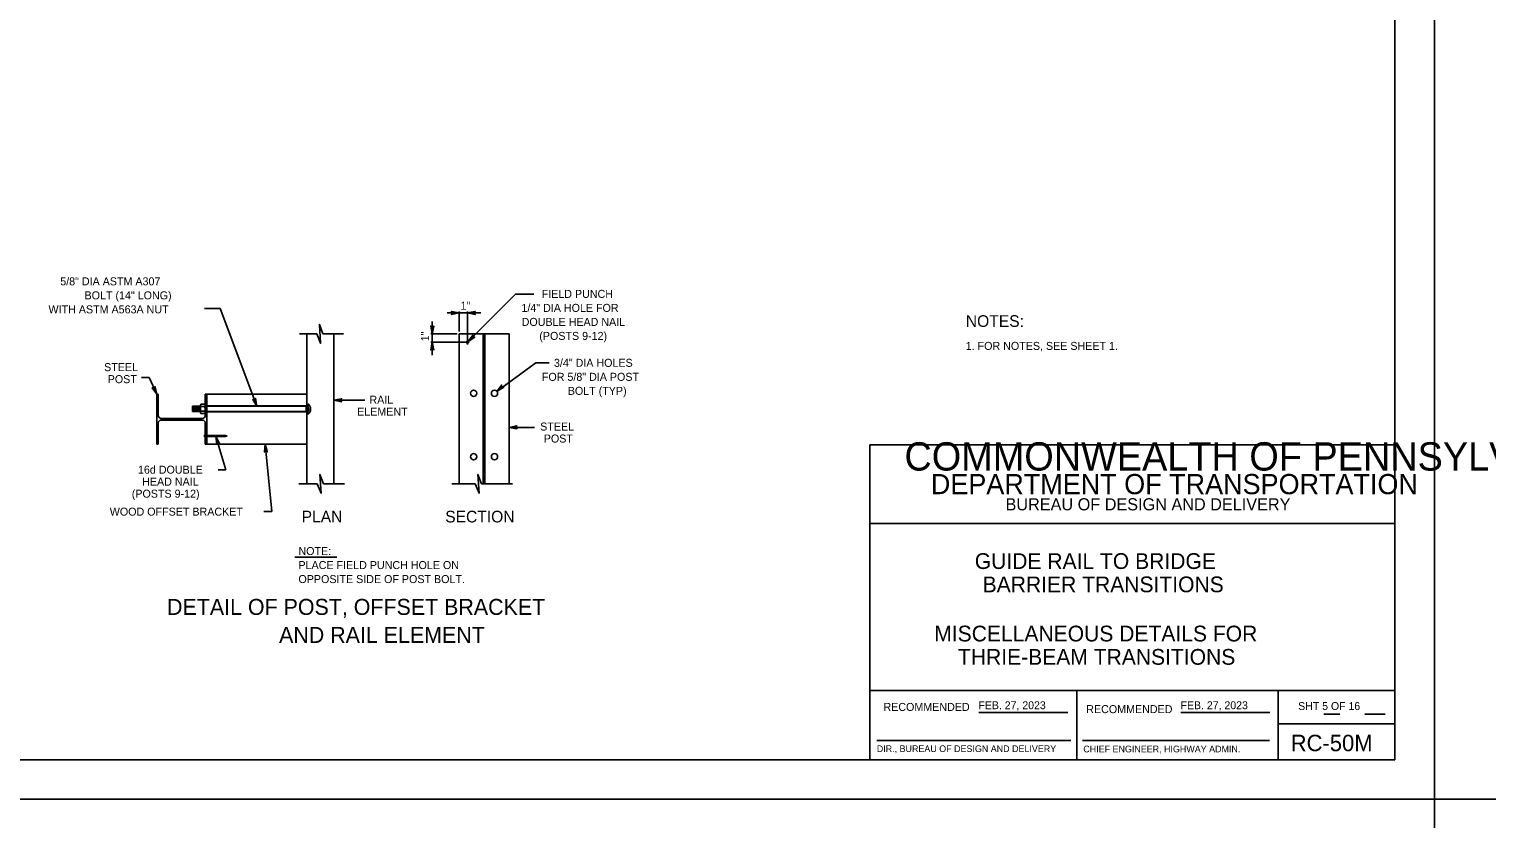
# Model space of a CAD drawing. Extents: x 632007860 to 635435983, y 295418622 to 297794622.
# Drawn here: x 633154598 to 633709860, y 297193122 to 297493872 of the extents above; entities that cross this region are included whole.
import ezdxf

# ---------------------------------------------------------------- set-up
doc = ezdxf.new("R2010")
doc.units = 0
for name, color, linetype in [('1', 7, 'Continuous'), ('2', 7, 'Continuous'), ('4', 7, 'Continuous'), ('8', 7, 'Continuous'), ('PLT-BNDY', 7, 'Continuous'), ('S-DETL-DIMS', 7, 'Continuous'), ('S-DETL-T120', 7, 'Continuous'), ('S-DETL-T175', 7, 'Continuous'), ('S-DETL-T240', 7, 'Continuous'), ('S-STEL', 7, 'Continuous')]:
    doc.layers.add(name, color=color, linetype=linetype)

msp = doc.modelspace()

# ---------------------------------------------------------------- linework, layer by layer
at = {"layer": '1'}
for p, q in [((633674860, 297779622), (633674860, 297215622)), ((633674860, 297335622), (633474860, 297335622)), ((633474860, 297335622), (633474860, 297215622)), ((633674860, 297305622), (633474860, 297305622)), ((633674860, 297241981), (633474860, 297241981)), ((633553661, 297241981), (633553661, 297215622)), ((633630362, 297241981), (633630362, 297215622)), ((633516325, 297233611), (633550211, 297233611)), ((633593323, 297233611), (633627193, 297233611)), ((633647751, 297232991), (633653893, 297232991)), ((633663427, 297232991), (633671073, 297232991)), ((633630362, 297229300), (633674860, 297229300)), ((633477485, 297222918), (633551385, 297222918)), ((633555791, 297222918), (633627131, 297222918)), ((633674860, 297215622), (632888860, 297215622))]:
    msp.add_line(p, q, dxfattribs=at)
at = {"layer": '4'}
msp.add_line((633674860, 297215622), (633674860, 297335622), dxfattribs=at)
at = {"layer": '8'}
for p, q in [((633321543, 297386319), (633321543, 297373807)), ((633307575, 297374671), (633322220, 297374671))]:
    msp.add_line(p, q, dxfattribs=at)
at = {"layer": 'PLT-BNDY'}
for points in [[(632848860, 297794622), (633689860, 297794622), (633689860, 297200622), (632848860, 297200622)], [(633689860, 297794622), (634530860, 297794622), (634530860, 297200622), (633689860, 297200622)], [(632848860, 297200622), (633689860, 297200622), (633689860, 296606622), (632848860, 296606622)], [(633689860, 297200622), (634530860, 297200622), (634530860, 296606622), (633689860, 296606622)]]:
    msp.add_lwpolyline(points, close=True, dxfattribs=at)
at = {"layer": 'S-DETL-DIMS'}
for p, q in [((633321867, 297374899), (633339865, 297392908)), ((633339865, 297392908), (633346851, 297392908)), ((633221416, 297387509), (633227417, 297387509)), ((633227417, 297387509), (633241365, 297350262)), ((633308154, 297382590), (633308154, 297369762)), ((633313856, 297385809), (633326612, 297385809)), ((633318370, 297378720), (633318370, 297386319)), ((633257604, 297377845), (633264140, 297377845)), ((633266521, 297377845), (633274387, 297377845)), ((633317648, 297377845), (633307575, 297377845)), ((633332810, 297355940), (633347545, 297366731)), ((633347545, 297366731), (633352662, 297366731)), ((633197435, 297361156), (633200307, 297361156)), ((633200307, 297361156), (633203201, 297354825)), ((633270659, 297352543), (633282501, 297352543)), ((633229477, 297326031), (633225743, 297338769)), ((633337420, 297342215), (633347032, 297342215)), ((633247091, 297310205), (633244447, 297335775)), ((633226605, 297326031), (633229477, 297326031)), ((633257329, 297320695), (633264330, 297320695)), ((633266711, 297320695), (633274703, 297320695)), ((633315661, 297320695), (633324547, 297320695)), ((633326929, 297320695), (633338686, 297320695)), ((633243995, 297310205), (633247091, 297310205))]:
    msp.add_line(p, q, dxfattribs=at)
for points in [[(633318370, 297385809), (633315410, 297385254), (633315524, 297385333), (633315638, 297385412), (633315697, 297385511), (633315756, 297385611), (633315773, 297385710), (633315790, 297385809), (633315773, 297385908), (633315756, 297386008), (633315697, 297386107), (633315638, 297386206), (633315524, 297386285), (633315410, 297386364), (633318370, 297385809), (633315524, 297386285), (633315638, 297386206), (633318370, 297385809), (633315697, 297386107), (633315756, 297386008), (633318370, 297385809), (633315773, 297385908), (633315790, 297385809), (633318370, 297385809), (633315773, 297385710), (633315756, 297385611), (633318370, 297385809), (633315697, 297385511), (633315638, 297385412), (633318370, 297385809), (633315524, 297385333)], [(633321543, 297385809), (633324503, 297386364), (633324389, 297386285), (633324275, 297386206), (633324216, 297386107), (633324157, 297386008), (633324140, 297385908), (633324123, 297385809), (633324140, 297385710), (633324157, 297385611), (633324216, 297385511), (633324275, 297385412), (633324389, 297385333), (633324503, 297385254), (633321543, 297385809), (633324389, 297385333), (633324275, 297385412), (633321543, 297385809), (633324216, 297385511), (633324157, 297385611), (633321543, 297385809), (633324140, 297385710), (633324123, 297385809), (633321543, 297385809), (633324140, 297385908), (633324157, 297386008), (633321543, 297385809), (633324216, 297386107), (633324275, 297386206), (633321543, 297385809), (633324389, 297386285)], [(633264140, 297377845), (633265590, 297374273), (633265158, 297381417), (633266521, 297377845)], [(633308154, 297377845), (633307599, 297380804), (633307678, 297380690), (633307757, 297380576), (633307856, 297380518), (633307955, 297380459), (633308054, 297380442), (633308154, 297380425), (633308253, 297380442), (633308352, 297380459), (633308451, 297380518), (633308551, 297380576), (633308630, 297380690), (633308709, 297380804), (633308154, 297377845), (633308630, 297380690), (633308551, 297380576), (633308154, 297377845), (633308451, 297380518), (633308352, 297380459), (633308154, 297377845), (633308253, 297380442), (633308154, 297380425), (633308154, 297377845), (633308054, 297380442), (633307955, 297380459), (633308154, 297377845), (633307856, 297380518), (633307757, 297380576), (633308154, 297377845), (633307678, 297380690)], [(633321867, 297374899), (633323567, 297377385), (633323542, 297377248), (633323517, 297377112), (633323546, 297377000), (633323575, 297376888), (633323633, 297376806), (633323691, 297376724), (633323773, 297376666), (633323855, 297376608), (633323967, 297376579), (633324079, 297376551), (633324215, 297376576), (633324352, 297376600), (633321867, 297374899), (633324215, 297376576), (633324079, 297376551), (633321867, 297374899), (633323967, 297376579), (633323855, 297376608), (633321867, 297374899), (633323773, 297376666), (633323691, 297376724), (633321867, 297374899), (633323633, 297376806), (633323575, 297376888), (633321867, 297374899), (633323546, 297377000), (633323517, 297377112), (633321867, 297374899), (633323542, 297377248)], [(633308154, 297374671), (633308709, 297371712), (633308630, 297371826), (633308551, 297371940), (633308451, 297371999), (633308352, 297372058), (633308253, 297372075), (633308154, 297372092), (633308054, 297372075), (633307955, 297372058), (633307856, 297371999), (633307757, 297371940), (633307678, 297371826), (633307599, 297371712), (633308154, 297374671), (633307678, 297371826), (633307757, 297371940), (633308154, 297374671), (633307856, 297371999), (633307955, 297372058), (633308154, 297374671), (633308054, 297372075), (633308154, 297372092), (633308154, 297374671), (633308253, 297372075), (633308352, 297372058), (633308154, 297374671), (633308451, 297371999), (633308551, 297371940), (633308154, 297374671), (633308630, 297371826)], [(633203201, 297354825), (633201466, 297357286), (633201585, 297357215), (633201705, 297357144), (633201819, 297357132), (633201934, 297357120), (633202031, 297357145), (633202129, 297357171), (633202212, 297357228), (633202295, 297357285), (633202361, 297357379), (633202427, 297357474), (633202451, 297357611), (633202476, 297357747), (633203201, 297354825), (633202451, 297357611), (633202427, 297357474), (633203201, 297354825), (633202361, 297357379), (633202295, 297357285), (633203201, 297354825), (633202212, 297357228), (633202129, 297357171), (633203201, 297354825), (633202031, 297357145), (633201934, 297357120), (633203201, 297354825), (633201819, 297357132), (633201705, 297357144), (633203201, 297354825), (633201585, 297357215)], [(633332810, 297355940), (633334612, 297358352), (633334581, 297358217), (633334551, 297358081), (633334575, 297357969), (633334599, 297357856), (633334653, 297357771), (633334708, 297357687), (633334788, 297357625), (633334868, 297357564), (633334978, 297357531), (633335088, 297357497), (633335226, 297357517), (633335363, 297357536), (633332810, 297355940), (633335226, 297357517), (633335088, 297357497), (633332810, 297355940), (633334978, 297357531), (633334868, 297357564), (633332810, 297355940), (633334788, 297357625), (633334708, 297357687), (633332810, 297355940), (633334653, 297357771), (633334599, 297357856), (633332810, 297355940), (633334575, 297357969), (633334551, 297358081), (633332810, 297355940), (633334581, 297358217)], [(633241365, 297350262), (633239808, 297352838), (633239922, 297352759), (633240036, 297352680), (633240149, 297352660), (633240263, 297352640), (633240362, 297352659), (633240461, 297352677), (633240548, 297352728), (633240635, 297352779), (633240707, 297352869), (633240779, 297352959), (633240813, 297353093), (633240847, 297353228), (633241365, 297350262), (633240813, 297353093), (633240779, 297352959), (633241365, 297350262), (633240707, 297352869), (633240635, 297352779), (633241365, 297350262), (633240548, 297352728), (633240461, 297352677), (633241365, 297350262), (633240362, 297352659), (633240263, 297352640), (633241365, 297350262), (633240149, 297352660), (633240036, 297352680), (633241365, 297350262), (633239922, 297352759)], [(633270659, 297352543), (633273619, 297353098), (633273505, 297353019), (633273390, 297352940), (633273332, 297352840), (633273273, 297352741), (633273256, 297352642), (633273239, 297352543), (633273256, 297352443), (633273273, 297352344), (633273332, 297352245), (633273390, 297352146), (633273505, 297352067), (633273619, 297351988), (633270659, 297352543), (633273505, 297352067), (633273390, 297352146), (633270659, 297352543), (633273332, 297352245), (633273273, 297352344), (633270659, 297352543), (633273256, 297352443), (633273239, 297352543), (633270659, 297352543), (633273256, 297352642), (633273273, 297352741), (633270659, 297352543), (633273332, 297352840), (633273390, 297352940), (633270659, 297352543), (633273505, 297353019)], [(633337420, 297342215), (633340379, 297342770), (633340265, 297342691), (633340151, 297342612), (633340092, 297342513), (633340033, 297342413), (633340016, 297342314), (633339999, 297342215), (633340016, 297342116), (633340033, 297342017), (633340092, 297341917), (633340151, 297341818), (633340265, 297341739), (633340379, 297341660), (633337420, 297342215), (633340265, 297341739), (633340151, 297341818), (633337420, 297342215), (633340092, 297341917), (633340033, 297342017), (633337420, 297342215), (633340016, 297342116), (633339999, 297342215), (633337420, 297342215), (633340016, 297342314), (633340033, 297342413), (633337420, 297342215), (633340092, 297342513), (633340151, 297342612), (633337420, 297342215), (633340265, 297342691)], [(633225743, 297338769), (633227108, 297336085), (633227000, 297336172), (633226892, 297336259), (633226780, 297336288), (633226668, 297336316), (633226568, 297336305), (633226468, 297336293), (633226378, 297336249), (633226288, 297336205), (633226209, 297336121), (633226130, 297336036), (633226086, 297335905), (633226043, 297335773), (633225743, 297338769), (633226086, 297335905), (633226130, 297336036), (633225743, 297338769), (633226209, 297336121), (633226288, 297336205), (633225743, 297338769), (633226378, 297336249), (633226468, 297336293), (633225743, 297338769), (633226568, 297336305), (633226668, 297336316), (633225743, 297338769), (633226780, 297336288), (633226892, 297336259), (633225743, 297338769), (633227000, 297336172)], [(633244447, 297335775), (633245298, 297332887), (633245208, 297332992), (633245118, 297333098), (633245013, 297333146), (633244908, 297333195), (633244808, 297333202), (633244707, 297333208), (633244610, 297333181), (633244513, 297333154), (633244421, 297333086), (633244328, 297333017), (633244261, 297332896), (633244194, 297332775), (633244447, 297335775), (633244261, 297332896), (633244328, 297333017), (633244447, 297335775), (633244421, 297333086), (633244513, 297333154), (633244447, 297335775), (633244610, 297333181), (633244707, 297333208), (633244447, 297335775), (633244808, 297333202), (633244908, 297333195), (633244447, 297335775), (633245013, 297333146), (633245118, 297333098), (633244447, 297335775), (633245208, 297332992)], [(633264330, 297320695), (633265779, 297317123), (633265347, 297324267), (633266711, 297320695)], [(633324547, 297320695), (633325997, 297317123), (633325565, 297324267), (633326929, 297320695)]]:
    msp.add_lwpolyline(points, dxfattribs=at)
at = {"layer": 'S-DETL-T120'}
msp.add_line((633255749, 297292765), (633271773, 297292765), dxfattribs=at)
at = {"layer": 'S-STEL'}
for p, q in [((633260342, 297377845), (633260342, 297320695)), ((633270659, 297377845), (633270659, 297320695)), ((633318370, 297377845), (633318370, 297320695)), ((633318370, 297377845), (633337420, 297377845)), ((633327597, 297377845), (633327597, 297320695)), ((633328192, 297377845), (633328192, 297320695)), ((633337420, 297377845), (633337420, 297320695)), ((633203201, 297354825), (633203201, 297335775)), ((633203795, 297354825), (633203201, 297354825)), ((633203795, 297354825), (633203795, 297346790)), ((633222251, 297354825), (633221657, 297354825)), ((633221657, 297354825), (633221657, 297346790)), ((633222251, 297354825), (633222251, 297335775)), ((633222251, 297354825), (633222251, 297335775)), ((633222251, 297354825), (633260342, 297354825)), ((633219840, 297350262), (633216764, 297350262)), ((633216764, 297350262), (633216764, 297348278)), ((633216996, 297349957), (633216996, 297348602)), ((633217228, 297350262), (633217228, 297348278)), ((633217460, 297349957), (633217460, 297348602)), ((633217692, 297350262), (633217692, 297348278)), ((633217924, 297349957), (633217924, 297348602)), ((633218155, 297350262), (633218155, 297348278)), ((633218387, 297349957), (633218387, 297348602)), ((633218619, 297350262), (633218619, 297348278)), ((633218851, 297349957), (633218851, 297348602)), ((633219083, 297350262), (633219083, 297348278)), ((633219314, 297349957), (633219314, 297348602)), ((633219546, 297350262), (633219546, 297348278)), ((633219778, 297349957), (633219778, 297348602)), ((633219840, 297350758), (633219840, 297350559)), ((633219840, 297350559), (633219840, 297349270)), ((633219840, 297349270), (633219840, 297347981)), ((633221415, 297350988), (633220038, 297350988)), ((633221415, 297350129), (633220038, 297350129)), ((633221415, 297348411), (633220038, 297348411)), ((633221611, 297350762), (633221611, 297347778)), ((633221611, 297350460), (633222241, 297350460)), ((633260341, 297350262), (633221611, 297350262)), ((633260341, 297350460), (633222241, 297350460)), ((633260075, 297350191), (633260075, 297348207)), ((633260341, 297350948), (633260341, 297347450)), ((633260341, 297350389), (633260769, 297350389)), ((633260769, 297350174), (633260769, 297351233)), ((633260769, 297350174), (633260785, 297350174)), ((633260769, 297350174), (633260769, 297348224)), ((633260785, 297350174), (633260785, 297351233)), ((633203795, 297343810), (633203795, 297335775)), ((633220558, 297345003), (633204877, 297345003)), ((633220558, 297345597), (633204894, 297345597)), ((633219840, 297348278), (633216764, 297348278)), ((633219840, 297347981), (633219840, 297347782)), ((633221415, 297347551), (633220038, 297347551)), ((633260446, 297348278), (633221633, 297348278)), ((633221633, 297348080), (633222264, 297348080)), ((633221657, 297343810), (633221657, 297335775)), ((633222241, 297348080), (633260341, 297348080)), ((633260341, 297348009), (633260769, 297348009)), ((633260785, 297348224), (633260769, 297348224)), ((633260769, 297347165), (633260769, 297348224)), ((633260785, 297347165), (633260785, 297348224)), ((633221639, 297339131), (633222019, 297339131)), ((633222019, 297338769), (633221639, 297338769)), ((633222109, 297339131), (633229376, 297339131)), ((633229376, 297338769), (633222109, 297338769)), ((633203201, 297335775), (633203795, 297335775)), ((633221657, 297335775), (633222251, 297335775)), ((633222251, 297335775), (633260342, 297335775))]:
    msp.add_line(p, q, dxfattribs=at)
for points in [[(633221369, 297338588), (633221369, 297338597), (633221369, 297338636), (633221369, 297338703), (633221369, 297338793), (633221369, 297338896), (633221369, 297339004), (633221369, 297339107), (633221369, 297339196), (633221369, 297339263), (633221369, 297339303), (633221369, 297339312)], [(633221460, 297338588), (633221460, 297338597), (633221460, 297338636), (633221460, 297338703), (633221460, 297338793), (633221460, 297338896), (633221460, 297339004), (633221460, 297339107), (633221460, 297339196), (633221460, 297339263), (633221460, 297339303), (633221460, 297339312)], [(633222019, 297338588), (633222019, 297338597), (633222019, 297338636), (633222019, 297338703), (633222019, 297338793), (633222019, 297338896), (633222019, 297339004), (633222019, 297339107), (633222019, 297339196), (633222019, 297339263), (633222019, 297339303), (633222019, 297339312)], [(633222109, 297338588), (633222109, 297338597), (633222109, 297338636), (633222109, 297338703), (633222109, 297338793), (633222109, 297338896), (633222109, 297339004), (633222109, 297339107), (633222109, 297339196), (633222109, 297339263), (633222109, 297339303), (633222109, 297339312)], [(633229376, 297339131), (633229376, 297338881), (633229376, 297338822), (633229376, 297338783), (633229376, 297338769)], [(633229935, 297338950), (633229935, 297338954), (633229935, 297338958), (633229935, 297338960), (633229935, 297338961)], [(633229935, 297338946), (633229935, 297338950), (633229935, 297338946), (633229935, 297338942), (633229935, 297338940), (633229935, 297338939), (633229935, 297338940), (633229935, 297338942), (633229935, 297338946)]]:
    msp.add_lwpolyline(points, dxfattribs=at)
for centre, radius in [((633321543, 297374671), 396), ((633323918, 297355221), 1191), ((633331861, 297355221), 1191), ((633323918, 297331012), 1191), ((633331861, 297331012), 1191)]:
    msp.add_circle(centre, radius, dxfattribs=at)
for centre, radius, start, end in [((633259287, 297349199), 2526, 306.37027, 53.62973), ((633259287, 297349199), 1788, 326.93176, 33.06824), ((633204941, 297346742), 1146, 177.61802, 267.61802), ((633204941, 297343858), 1146, 92.38198, 182.38198), ((633220510, 297346742), 1146, 272.38198, 2.38198), ((633220510, 297343858), 1146, 357.61802, 87.61802)]:
    msp.add_arc(centre, radius, start, end, dxfattribs=at)
for points, degree in [([(633219840, 297350758), (633220038, 297350988)], 1), ([(633220038, 297350129), (633219987, 297350194), (633219888, 297350318), (633219840, 297350479), (633219840, 297350557), (633219840, 297350559)], 3), ([(633219840, 297349270), (633219840, 297349290), (633219842, 297349419), (633219874, 297349659), (633219954, 297349924), (633220017, 297350079), (633220038, 297350129)], 3), ([(633220038, 297348411), (633220009, 297348483), (633219939, 297348656), (633219859, 297348942), (633219846, 297349160), (633219840, 297349270)], 3), ([(633219840, 297347981), (633219848, 297348042), (633219865, 297348173), (633219956, 297348311), (633220019, 297348387), (633220038, 297348411)], 3), ([(633221415, 297350988), (633221611, 297350762)], 1), ([(633221415, 297350129), (633221467, 297350194), (633221566, 297350318), (633221613, 297350479), (633221614, 297350557), (633221614, 297350559)], 3), ([(633221614, 297349270), (633221614, 297349290), (633221612, 297349419), (633221579, 297349659), (633221500, 297349924), (633221436, 297350079), (633221415, 297350129)], 3), ([(633221415, 297348411), (633221445, 297348483), (633221515, 297348656), (633221595, 297348942), (633221607, 297349160), (633221614, 297349270)], 3), ([(633221614, 297347981), (633221606, 297348042), (633221588, 297348173), (633221498, 297348311), (633221435, 297348387), (633221415, 297348411)], 3), ([(633221611, 297350262), (633221614, 297350262)], 1), ([(633260075, 297350191), (633260670, 297350191)], 1), ([(633260670, 297350191), (633260671, 297350191), (633260700, 297350190), (633260753, 297350179), (633260765, 297350136), (633260769, 297350122)], 3), ([(633260670, 297350191), (633260675, 297350191)], 1), ([(633260769, 297351233), (633260785, 297351233)], 1), ([(633220038, 297347551), (633219840, 297347782)], 1), ([(633221611, 297347778), (633221415, 297347551)], 1), ([(633221614, 297348278), (633221611, 297348278)], 1), ([(633260670, 297348207), (633260075, 297348207)], 1), ([(633260769, 297348276), (633260765, 297348262), (633260753, 297348219), (633260700, 297348207), (633260671, 297348207), (633260670, 297348207)], 3), ([(633260675, 297348207), (633260670, 297348207)], 1), ([(633260785, 297347165), (633260769, 297347165)], 1), ([(633221460, 297339312), (633221369, 297339312)], 1), ([(633221369, 297338588), (633221460, 297338588)], 1), ([(633221639, 297339131), (633221460, 297339131)], 1), ([(633221460, 297338769), (633221639, 297338769)], 1), ([(633222109, 297339312), (633222019, 297339312)], 1), ([(633222019, 297338588), (633222109, 297338588)], 1), ([(633229935, 297338961), (633229842, 297338989), (633229655, 297339044), (633229469, 297339102), (633229376, 297339131)], 3), ([(633229376, 297338769), (633229469, 297338798), (633229655, 297338856), (633229842, 297338911), (633229935, 297338939)], 3)]:
    msp.add_open_spline(points, degree=degree, dxfattribs=at)

# ---------------------------------------------------------------- texts
at = {"layer": '1'}
for s, height, p in [('COMMONWEALTH OF PENNSYLVANIA', 10783.37, (633488011, 297325766)), ('DEPARTMENT OF TRANSPORTATION', 7684.29, (633498072, 297316771)), ('BUREAU OF DESIGN AND DELIVERY', 4622.09, (633526520, 297310609)), ('RECOMMENDED', 3048, (633480023, 297234216)), ('FEB. 27, 2023', 3000, (633516186, 297234887)), ('FEB. 27, 2023', 3000, (633593184, 297234887)), ('SHT 5 OF 16', 3000, (633637991, 297234576)), ('APPROVED', 19.2, (633517883, 297233554)), ('RECOMMENDED', 3048, (633557267, 297233379)), ('DIR., BUREAU OF DESIGN AND DELIVERY', 2540, (633477485, 297218554)), ('CHIEF ENGINEER, HIGHWAY ADMIN.', 2540, (633556144, 297218445)), ('RC-50M', 6267.5, (633635143, 297218881))]:
    msp.add_text(s, height=height, dxfattribs=at).set_placement(p)
at = {"layer": '2'}
for s, p in [('GUIDE RAIL TO BRIDGE', (633514804, 297288287)), ('BARRIER TRANSITIONS', (633517804, 297279412))]:
    msp.add_text(s, height=6000, dxfattribs=at).set_placement(p)
at = {"layer": '4'}
for s, p in [('MISCELLANEOUS DETAILS FOR', (633499376, 297260686)), ('THRIE-BEAM TRANSITIONS', (633508400, 297251804))]:
    msp.add_text(s, height=6000, dxfattribs=at).set_placement(p)
at = {"layer": 'S-DETL-T120'}
for s, height, p in [(' 5/8" DIA ASTM A307', 3048.07, (633165307, 297396302)), ('BOLT (14" LONG)', 3048.07, (633175700, 297390968)), ('FIELD PUNCH', 3048.07, (633349826, 297391527)), ('WITH ASTM A563A NUT', 3048.07, (633161971, 297385634)), ('1"', 3048.1, (633318899, 297387027)), ('1/4" DIA HOLE FOR', 3048.07, (633342122, 297386193)), ('DOUBLE HEAD NAIL', 3048.07, (633342206, 297380859)), ('(POSTS 9-12)', 3048.07, (633348927, 297375525)), ('STEEL', 3048.1, (633183155, 297363622)), ('3/4" DIA HOLES', 3048.07, (633354513, 297365271)), ('POST', 3048.1, (633184523, 297359050)), ('FOR 5/8" DIA POST', 3048.07, (633349905, 297359937)), ('RAIL', 3048.1, (633284212, 297351223)), ('BOLT (TYP)', 3048.1, (633359769, 297354603)), ('ELEMENT', 3048.1, (633279531, 297346651)), ('STEEL', 3048.1, (633349258, 297341002)), ('POST', 3048.1, (633350626, 297336430)), ('16d DOUBLE', 3048.1, (633196049, 297324577)), ('HEAD NAIL', 3048.1, (633197645, 297320005)), ('(POSTS 9-12)', 3048.07, (633193697, 297315433)), ('WOOD OFFSET BRACKET', 3048.07, (633185306, 297308586)), ('NOTE:', 3048.1, (633257177, 297293581)), ('PLACE FIELD PUNCH HOLE ON', 3048.07, (633257177, 297288246)), ('OPPOSITE SIDE OF POST BOLT.', 3048.07, (633257177, 297282912))]:
    msp.add_text(s, height=height, dxfattribs=at).set_placement(p)
for s, height, rotation, p in [('1"', 3048.1, 90, (633306932, 297374991)), ('1. FOR NOTES, SEE SHEET 1.', 3048.06, 360, (633511347, 297371717))]:
    msp.add_text(s, height=height, rotation=rotation, dxfattribs=at).set_placement(p)
at = {"layer": 'S-DETL-T175'}
for s, height, p in [('NOTES:', 4450, (633511390, 297380482)), ('PLAN', 4442.5, (633258397, 297306006)), ('SECTION', 4442.5, (633313086, 297306006))]:
    msp.add_text(s, height=height, dxfattribs=at).set_placement(p)
at = {"layer": 'S-DETL-T240'}
for s, p in [('DETAIL OF POST, OFFSET BRACKET', (633207129, 297270787)), ('AND RAIL ELEMENT', (633249801, 297260119))]:
    msp.add_text(s, height=6096, dxfattribs=at).set_placement(p)

doc.saveas('drawing.dxf')
